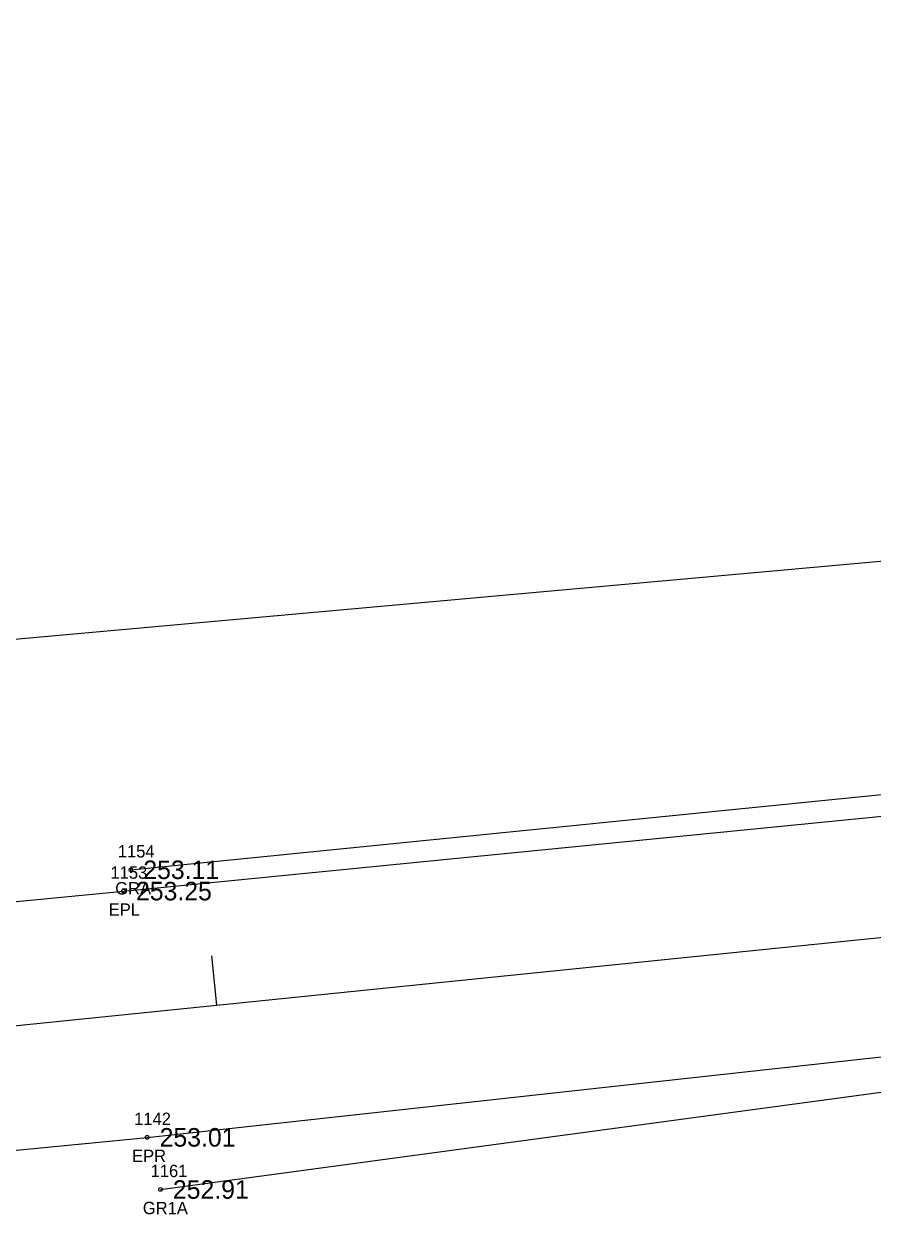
# Model space of a CAD drawing. Extents: x 2274993 to 2278766, y 1075634 to 1076749.
# Drawn here: x 2276227.1 to 2276295.7, y 1076041.3 to 1076138.8 of the extents above; entities that cross this region are included whole.
import ezdxf

# ---------------------------------------------------------------- set-up
doc = ezdxf.new("R2010")
doc.units = 0
for name, color, linetype in [('RD_EX_GuardRail', 7, 'Continuous'), ('RD_EX_GuardRail_txCode', 7, 'Continuous'), ('RD_EX_Road', 7, 'Continuous'), ('RD_EX_Road_txCode', 7, 'Continuous'), ('RD_EX_TX_GuardRail_ELEV', 7, 'Continuous'), ('RD_EX_TX_Road_ELEV', 7, 'Continuous'), ('RD_EX_VEG', 7, 'Continuous'), ('RD_HC_Cl', 7, 'Continuous'), ('RD_HC_Data_Tic', 7, 'Continuous'), ('RD_SMD_Locator', 7, 'Continuous')]:
    doc.layers.add(name, color=color, linetype=linetype)

msp = doc.modelspace()

# ---------------------------------------------------------------- linework, layer by layer
at = {"layer": 'RD_EX_GuardRail'}
for points in [[(2276235.721, 1076070.406), (2276318.745, 1076078.742), (2276379.223, 1076085.124), (2276462.209, 1076096.64)], [(2276238.114, 1076044.539), (2276321.323, 1076055.787), (2276381.246, 1076062.041), (2276465.669, 1076068.187)]]:
    msp.add_lwpolyline(points, dxfattribs=at)
at = {"layer": 'RD_EX_Road'}
for points in [[(2275577.734, 1075970.549), (2275625.953, 1075985.495), (2275674.013, 1075998.037), (2275722.504, 1076008.983), (2275771.646, 1076017.818), (2275820.475, 1076025.098), (2275865.7, 1076030.611), (2275949.165, 1076039.364), (2275965.188, 1076041.067), (2276054.281, 1076050.491), (2276149.421, 1076060.387), (2276235.129, 1076068.681), (2276318.867, 1076076.963)], [(2275583.237, 1075951.044), (2275629.663, 1075965.928), (2275678.063, 1075978.684), (2275725.565, 1075989.059), (2275775.662, 1075998.229), (2275820.793, 1076005.148), (2275867.875, 1076010.757), (2275970.822, 1076021.78), (2276056.639, 1076030.613), (2276150.8, 1076040.386), (2276237.042, 1076048.757), (2276320.71, 1076057.946)]]:
    msp.add_lwpolyline(points, dxfattribs=at)
at = {"layer": 'RD_EX_VEG'}
msp.add_lwpolyline([(2276059.586, 1076114.414), (2276109.623, 1076078.547), (2276326.545, 1076098.097), (2276364.639, 1076103.942), (2276468.167, 1076112.629), (2276687.38, 1076155.016), (2276867.984, 1076201.611), (2276854.55, 1076228.931)], dxfattribs=at)
at = {"layer": 'RD_HC_Cl'}
msp.add_line((2275853.326, 1076019.717), (2276414.602, 1076077.005), dxfattribs=at)
at = {"layer": 'RD_HC_Data_Tic'}
msp.add_line((2276242.672, 1076059.456), (2276242.266, 1076063.436), dxfattribs=at)
at = {"layer": 'RD_SMD_Locator'}
for centre in [(2276235.721, 1076070.406), (2276235.129, 1076068.681), (2276237.042, 1076048.757), (2276238.114, 1076044.539)]:
    msp.add_circle(centre, 0.15, dxfattribs=at)

# ---------------------------------------------------------------- texts
at = {"layer": 'RD_EX_GuardRail_txCode'}
for s, p in [('1154', (2276234.658, 1076071.406)), ('GRA', (2276234.453, 1076068.406)), ('1161', (2276237.311, 1076045.539)), ('GR1A', (2276236.681, 1076042.539))]:
    msp.add_text(s, height=1, dxfattribs=at).set_placement(p)
at = {"layer": 'RD_EX_Road_txCode'}
for s, p in [('1153', (2276234.066, 1076069.681)), ('EPL', (2276233.924, 1076066.681)), ('1142', (2276235.979, 1076049.757)), ('EPR', (2276235.813, 1076046.757))]:
    msp.add_text(s, height=1, dxfattribs=at).set_placement(p)
at = {"layer": 'RD_EX_TX_GuardRail_ELEV'}
for s, p in [('253.11', (2276236.721, 1076069.656)), ('252.91', (2276239.114, 1076043.789))]:
    msp.add_text(s, height=1.5, dxfattribs=at).set_placement(p)
at = {"layer": 'RD_EX_TX_Road_ELEV'}
for s, p in [('253.25', (2276236.129, 1076067.931)), ('253.01', (2276238.042, 1076048.007))]:
    msp.add_text(s, height=1.5, dxfattribs=at).set_placement(p)

doc.saveas('drawing.dxf')
